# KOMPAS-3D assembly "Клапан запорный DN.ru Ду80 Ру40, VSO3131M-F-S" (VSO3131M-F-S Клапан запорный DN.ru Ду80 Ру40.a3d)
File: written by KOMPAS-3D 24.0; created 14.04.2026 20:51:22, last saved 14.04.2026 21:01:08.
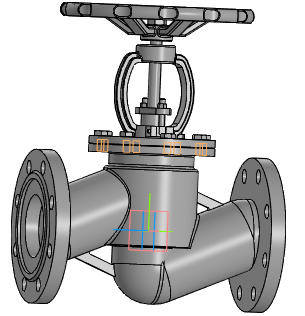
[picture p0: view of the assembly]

Document properties: Автор: R2D2; Полное имя файла: E:\Работа\Зайцев\VSO3131M-F-S Клапан запорный DN.ru Ду15-100 Ру40\DN80\исходные материалы\VSO3131M-F-S Клапан запорный DN.ru Ду80 Ру40.a3d

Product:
- Component [detail]: Корпус  | qty 1  | pos. 1  | Масса: 6.9; Автор: R2D2; source file: Корпус.m3d
- Component [detail]: Клапан запорный DN.ru Ду80 Ру16  | designation VSO1121M-F-S  | qty 1  | pos. 2  | Масса: 28.77; Раздел спецификации: Прочие изделия; Примечание: D090-01949; Автор: R2D2; source file: 2.m3d
- Part/product: Клапан запорный DN.ru Ду80 Ру40  | designation VSO3131M-F-S
    Масса: 22.29
    Раздел спецификации: Прочие изделия
    Примечание: D090-02144

Referenced files in E:\Работа\Зайцев\VSO3131M-F-S Клапан запорный DN.ru Ду15-100 Ру40\DN80\исходные материалы\: Корпус.m3d, 2.m3d
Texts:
  VSO3131M-F-S
  VSO1121M-F-S Клапан запорный DN.ru Ду80 Ру16
  Плоскость ZY.Начало координат
  Ось Y.Начало координат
